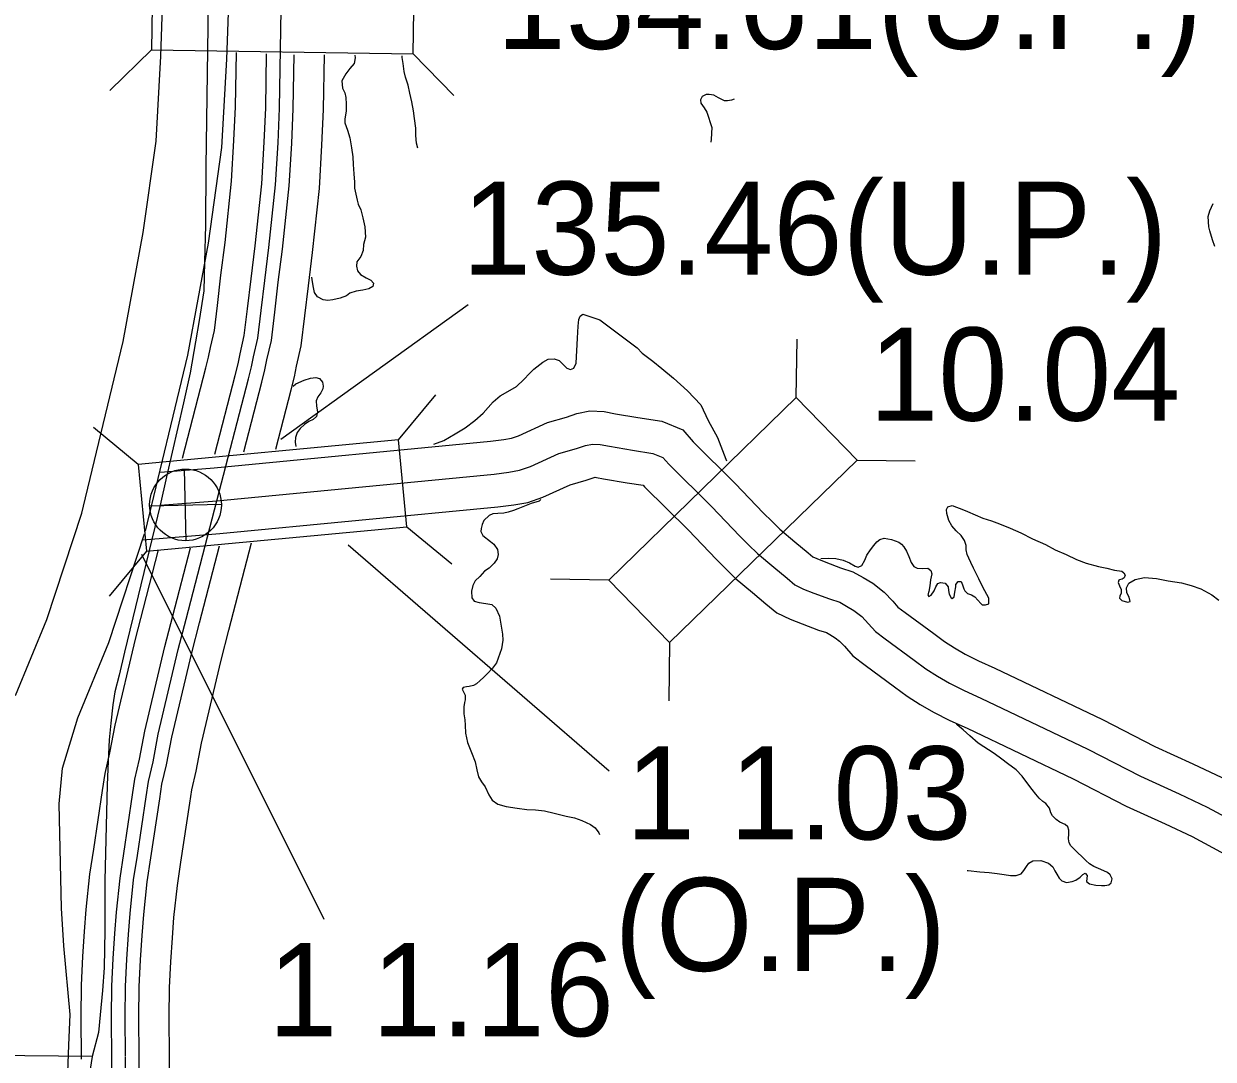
# Model space of a CAD drawing. Extents: x 31699 to 244310, y -8841 to 11474.
# Drawn here: x 103747.3 to 104107.3, y 350.4 to 663.7 of the extents above; entities that cross this region are included whole.
import ezdxf

# ---------------------------------------------------------------- set-up
doc = ezdxf.new("R2010")
doc.units = 0
for name, color, linetype in [('B_Logo', 7, 'Continuous'), ('Level 21', 7, 'Continuous'), ('New Level (0)', 7, 'Continuous'), ('R_Draft', 7, 'Continuous'), ('R_XS_EARTHWORK_STAGE1', 7, 'Continuous'), ('R_XS_EARTHWORK_STAGE2', 7, 'Continuous'), ('S_WALL', 7, 'Continuous'), ('S_WALL_ANNOT', 7, 'Continuous')]:
    doc.layers.add(name, color=color, linetype=linetype)

msp = doc.modelspace()

# ---------------------------------------------------------------- linework, layer by layer
at = {"layer": 'B_Logo'}
for points in [[(103803.15, 669.98), (103802.47, 620.45), (103802.33, 602.81), (103802.07, 591.65), (103801.83, 582.89), (103800.46, 573.97), (103799.31, 567.47), (103797.69, 558.15), (103795.72, 549.03), (103790.53, 526.68), (103788.63, 518.02), (103777.84, 473.64), (103776.24, 466.66), (103774.87, 461.63), (103774.27, 457.61), (103773.71, 452.11), (103773.13, 447.09), (103772.85, 440.61), (103772.59, 433.45), (103771.86, 404.5), (103771.87, 389.47), (103771.68, 378.04), (103771.14, 371.28), (103770.48, 363.91), (103769.91, 358.56), (103768.04, 351.3), (103761.18, 307.6)], [(103778.1, 351.48), (103778.03, 363.19), (103778.12, 372.48), (103778.5, 380.7), (103779.03, 388.13), (103779.51, 394.56), (103780.59, 404.67), (103781.72, 412.04), (103784.39, 429.86), (103785.04, 434.42), (103786.47, 440.39), (103788.04, 448.78), (103794.11, 474.35), (103796.47, 483.55), (103805.81, 519.41), (103815.33, 556.28), (103816.26, 559.91), (103816.87, 562.92), (103818.17, 568.63), (103819.22, 576.94), (103820.25, 586.04), (103821.53, 596.02), (103823.51, 614.97), (103824.28, 627.68), (103824.75, 638.18), (103825.2, 667.93)], [(103788.63, 518.02), (103805.81, 519.41), (103889.71, 527.48), (103894.1, 528.03), (103897.42, 528.63), (103900.74, 529.76), (103909.27, 533.67), (103914.58, 535.17), (103917.36, 536.09), (103919.49, 536.53), (103921.82, 536.44), (103924.64, 535.9), (103931.59, 534.69), (103937.75, 533.74), (103940.77, 532.53), (103942.55, 530.42), (103955.52, 517.64), (103964.1, 508.64), (103966.68, 506.09), (103969.4, 503.4), (103974.34, 499.28), (103978.34, 495.95), (103980.71, 493.99), (103983.34, 492.7), (103986.49, 491.49), (103991.2, 489.71), (103994.28, 488.7), (103996.37, 487.54), (103998.6, 486.18), (104000.97, 484.35), (104003.01, 482.18), (104005.12, 479.88), (104008.03, 477.6), (104016.82, 471.15), (104020.34, 468.54), (104023.85, 466.34), (104027.49, 464.2), (104031.93, 461.95), (104037.05, 459.64), (104069.35, 444.21), (104085.31, 436.03), (104097.02, 430.7), (104105.49, 426.72), (104118.09, 419.94)], [(103768.04, 351.3), (103625.41, 352.68)], [(103866.47, 45.97), (103832.32, 83.49), (103822.44, 94.79), (103816.44, 101.56), (103813.71, 104.85), (103810.89, 109.28), (103806.84, 115.55), (103802.08, 124.01), (103799.03, 130.3), (103794.94, 138.71), (103790.77, 147.52), (103787.51, 157.95), (103784, 170.78), (103782.49, 177.03), (103780.58, 186.08), (103779.27, 195.82), (103778.18, 207.96), (103777.62, 220.24), (103778.35, 252.73), (103778.59, 271.92), (103778.52, 297.11), (103778.21, 331.78), (103778.1, 351.23)]]:
    msp.add_lwpolyline(points, dxfattribs=at)
at = {"layer": 'Level 21'}
for p, q in [((103796.53, 507.3), (103796.03, 529)), ((103785.43, 517.9), (103807.13, 518.4))]:
    msp.add_line(p, q, dxfattribs=at)
msp.add_circle((103796.28, 518.15), 10.85, dxfattribs=at)
at = {"layer": 'New Level (0)'}
for points in [[(103795.37, 532.32), (103802.42, 559.61), (103803.26, 562.89), (103803.84, 565.72), (103805.02, 570.94), (103805.98, 578.52), (103807.01, 587.64), (103808.28, 597.57), (103810.22, 616.07), (103810.96, 628.38), (103811.42, 638.58), (103811.67, 655.01)], [(103805.15, 533.51), (103811.3, 557.32), (103812.2, 560.84), (103812.8, 563.8), (103814.06, 569.35), (103815.08, 577.43), (103816.11, 586.54), (103817.39, 596.51), (103819.36, 615.31), (103820.12, 627.9), (103820.58, 638.31), (103820.83, 654.63)], [(103813.94, 534.22), (103819.37, 555.24), (103820.33, 558.97), (103820.95, 562.05), (103822.28, 567.91), (103823.35, 576.44), (103824.38, 585.54), (103825.67, 595.54), (103827.67, 614.63), (103828.44, 627.47), (103828.91, 638.06), (103829.16, 654.28)], [(103823.6, 534.98), (103828.24, 552.95), (103829.26, 556.92), (103829.91, 560.13), (103831.32, 566.31), (103832.45, 575.35), (103833.48, 584.44), (103834.77, 594.48), (103836.8, 613.88), (103837.59, 626.98), (103838.08, 637.78), (103838.33, 654.27)], [(103764.77, 350.45), (103764.69, 363.22), (103764.79, 372.85), (103765.19, 381.49), (103765.73, 389.1), (103766.23, 395.76), (103767.37, 406.39), (103768.54, 414.04), (103771.2, 431.79), (103771.93, 436.91), (103773.42, 443.18), (103775, 451.55), (103781.16, 477.55), (103783.56, 486.89), (103788.16, 504.53)], [(103773.94, 350.45), (103773.86, 363.2), (103773.96, 372.59), (103774.34, 380.95), (103774.88, 388.43), (103775.36, 394.93), (103776.46, 405.2), (103777.6, 412.66), (103780.27, 430.47), (103780.95, 435.2), (103782.39, 441.26), (103783.97, 449.64), (103790.06, 475.35), (103792.44, 484.6), (103797.8, 505.2)], [(103782.27, 351.22), (103782.2, 363.18), (103782.29, 372.36), (103782.66, 380.46), (103783.19, 387.83), (103783.66, 394.18), (103784.73, 404.13), (103785.84, 411.41), (103788.52, 429.26), (103789.14, 433.64), (103790.54, 439.53), (103792.12, 447.91), (103798.15, 473.35), (103800.5, 482.51), (103806.55, 505.74)], [(103791.43, 351.22), (103791.36, 363.16), (103791.45, 372.1), (103791.81, 379.92), (103792.33, 387.16), (103792.79, 393.35), (103793.82, 402.95), (103794.91, 410.04), (103797.59, 427.94), (103798.16, 431.93), (103799.51, 437.61), (103801.09, 446.01), (103807.05, 471.16), (103809.38, 480.21), (103816.26, 506.63)], [(103860.79, 46.02), (103829.21, 80.71), (103819.31, 92.04), (103813.28, 98.85), (103810.34, 102.39), (103807.39, 107.03), (103803.27, 113.39), (103798.39, 122.08), (103795.28, 128.48), (103791.18, 136.91), (103786.88, 146), (103783.51, 156.78), (103779.97, 169.74), (103778.42, 176.11), (103776.48, 185.38), (103775.13, 195.35), (103774.02, 207.68), (103773.45, 220.19), (103774.18, 252.81), (103774.42, 271.94), (103774.36, 297.08), (103774.05, 331.75), (103773.94, 350.45)], [(103872.8, 45.21), (103835.43, 86.26), (103825.56, 97.55), (103819.6, 104.27), (103817.09, 107.31), (103814.4, 111.53), (103810.41, 117.7), (103805.78, 125.94), (103802.78, 132.12), (103798.7, 140.51), (103794.66, 149.04), (103791.51, 159.12), (103788.04, 171.82), (103786.55, 177.95), (103784.69, 186.79), (103783.41, 196.28), (103782.34, 208.24), (103781.78, 220.29), (103782.51, 252.66), (103782.76, 271.89), (103782.69, 297.13), (103782.38, 331.81), (103782.27, 351.22)], [(103884.83, 45.62), (103842.27, 92.36), (103832.45, 103.6), (103826.56, 110.24), (103824.51, 112.72), (103822.12, 116.47), (103818.26, 122.44), (103813.9, 130.19), (103811.02, 136.13), (103806.96, 144.48), (103803.22, 152.38), (103800.31, 161.7), (103796.92, 174.11), (103795.49, 179.98), (103793.73, 188.35), (103792.52, 197.31), (103791.48, 208.86), (103790.96, 220.4), (103791.68, 252.5), (103791.92, 271.85), (103791.86, 297.18), (103791.54, 331.88), (103791.43, 351.22)]]:
    msp.add_lwpolyline(points, dxfattribs=at)
at = {"layer": 'R_Draft'}
for points in [[(103847.5, 654.18), (103847.61, 653.45), (103847.31, 651.71), (103846.07, 650.22), (103844.77, 648.52), (103843.61, 646.43), (103843.85, 644.23), (103844.54, 642.77), (103844.77, 641.44), (103844.94, 639.37), (103844.91, 637.23), (103844.55, 634.95), (103844.51, 633.75), (103845.28, 631.49), (103845.99, 629.16), (103846.52, 626.17), (103846.9, 623.43), (103847.01, 621.16), (103847.2, 618.29), (103847.44, 615.76), (103847.48, 613.96), (103848.28, 610.36), (103848.57, 609.17), (103849.33, 607.38), (103849.98, 604.98), (103850.56, 602.25), (103850.75, 599.12), (103850.19, 596.97), (103850.03, 595.16), (103849.33, 593.28), (103848.16, 591.72), (103848.05, 590.38), (103848.34, 588.98), (103849.23, 587.86), (103850.98, 586.83), (103852.33, 586.18), (103853.15, 585.26), (103852.96, 584.26), (103851.78, 583.5), (103849.92, 583.13), (103847.92, 582.82), (103846.07, 582.19), (103845.01, 581.43), (103843.09, 580.73), (103840.9, 580.15), (103839.37, 579.99), (103837.96, 580.23), (103836.28, 581.07), (103835.32, 582.45), (103834.88, 584.45)], [(103866.58, 626.07), (103866.23, 627.54), (103865.99, 629.94), (103865.95, 632.15), (103865.63, 635.02), (103865.25, 637.41), (103864.8, 640.08), (103864.22, 642.67), (103863.64, 645.13), (103862.86, 647.53), (103862.43, 649.26), (103862.12, 651.65), (103861.88, 653.52), (103861.85, 654.02)], [(103962.36, 640.89), (103961.51, 640.57), (103960.31, 640.42), (103959.38, 640.4), (103957.63, 641.3), (103956.21, 642.08), (103954.74, 642.32), (103953.88, 642.3), (103952.69, 641.67), (103952.17, 640.73), (103952.26, 639.66), (103953.28, 638.28), (103954.04, 636.96), (103955.6, 632.31), (103955.39, 628.83), (103955.31, 627.85)], [(104107.81, 596.3), (104107.11, 598.29), (104106.32, 601.08), (104106.04, 602.28), (104105.84, 605.35), (104106.28, 607.09), (104107.37, 609.32)], [(103834.88, 584.45), (103834.65, 586.32), (103834.53, 587.09)], [(103871.49, 536.53), (103874.44, 537.62), (103877.87, 539.62), (103880.91, 541.42), (103883.87, 543.68), (103886.36, 545.93), (103889.37, 549.33), (103891.53, 551.17), (103893.84, 552.42), (103896.42, 553.94), (103898.71, 556.05), (103900.41, 557.89), (103901.72, 559.25), (103904.42, 561.37), (103906, 562.21), (103907.87, 562.37), (103909.34, 561.87), (103910.7, 560.56), (103911.72, 559.51), (103912.8, 559.13), (103913.86, 559.55), (103914.56, 561.03), (103914.89, 568.59), (103915.09, 572.2), (103915.38, 574.28), (103915.77, 575.29), (103916.55, 575.9), (103921.72, 574.13), (103933.02, 565.66), (103934.52, 564.08), (103937.7, 561.6), (103940.47, 559.45), (103944, 556.51), (103948.2, 552.65), (103952.22, 548.38), (103954.51, 543.68), (103957.27, 538.52), (103959.86, 531.95), (103960.03, 531.47)], [(103828.92, 554.08), (103829.7, 554.75), (103832.21, 555.93), (103834.07, 556.5), (103835.73, 556.67), (103836.81, 556.35), (103837.76, 555.23), (103837.98, 554.1), (103837.87, 553.23), (103837.22, 552.02), (103836.38, 550.8), (103835.86, 549.65), (103835.96, 548.05), (103836.26, 546.32), (103835.89, 544.91), (103834.9, 544.02), (103833.65, 543.33), (103832.33, 542.43), (103830.95, 541.27), (103830.04, 540.05), (103829.53, 538.51), (103829.49, 537.1), (103829.66, 535.8)], [(103903.83, 519.77), (103903.33, 519.25), (103900.88, 518.61), (103896.84, 516.99), (103895.51, 516.5), (103893.99, 515.94), (103892.59, 515.64), (103890.86, 515.54), (103889.33, 515.45), (103888.21, 514.89), (103886.57, 513.39), (103886.05, 512.18), (103885.74, 511.04), (103885.69, 510.1), (103886.32, 508.91), (103888.55, 507.08), (103889.63, 506.3), (103890.73, 504.65), (103890.96, 503.12), (103890.65, 501.84), (103889.67, 500.49), (103888.17, 499.05), (103886.78, 498.09), (103885.34, 496.53), (103883.97, 495.17), (103883.2, 493.75), (103882.89, 492.07), (103882.93, 490.07), (103883.68, 489.01), (103885.16, 488.57), (103887.23, 488.34), (103889.04, 487.98), (103890.26, 486.86), (103891.31, 484.48), (103891.83, 481.48), (103892.21, 479.08), (103892.37, 477.21), (103891.89, 474.6), (103890.43, 470.36), (103889.19, 468.8), (103887.69, 467.1), (103886.45, 465.88)], [(103988.53, 501.96), (103990.9, 502.07), (103993.1, 501.91), (103995.38, 501.42), (103997.26, 500.58), (103998.95, 499.61), (103999.89, 499.3), (104001.01, 499.79), (104001.85, 501.41), (104002.49, 502.95), (104003.59, 504.51), (104004.57, 505.87), (104005.48, 506.95), (104006.47, 507.71), (104007.73, 508.07), (104010.01, 507.71), (104012.16, 506.88), (104012.97, 506.29), (104013.65, 505.5), (104014.54, 504.12), (104015.17, 502.53), (104015.94, 500.67), (104016.69, 499.55), (104017.71, 498.97), (104019.24, 498.86), (104020.97, 498.96), (104021.85, 498.31), (104022.14, 497.25), (104021.77, 495.5), (104021.54, 493.63), (104021.24, 491.95), (104020.92, 490.94), (104021.26, 490.48), (104021.99, 490.83), (104022.9, 492.18), (104023.41, 493.39), (104023.99, 494.34), (104024.79, 494.69), (104026.19, 494.45), (104027.08, 493.4), (104027.17, 492.2), (104027.39, 491.13), (104028.01, 490.07), (104028.28, 489.81), (104028.94, 490.36), (104029.18, 491.77), (104029.42, 493.31), (104029.47, 494.04), (104030.19, 494.99), (104031.05, 495.01), (104031.47, 494.01), (104031.83, 492.75), (104032.11, 492.16), (104032.92, 491.3), (104034.13, 490.92), (104035.21, 490.34), (104036.09, 489.36), (104036.98, 488.31), (104037.45, 487.91), (104038.46, 487.87), (104039.38, 488.22), (104039.42, 489.95), (104038.24, 492.14), (104037.14, 494.26), (104036.37, 495.78), (104035.47, 497.63), (104034.78, 499.02), (104033.95, 500.68), (104033.32, 502.07), (104032.84, 503.13), (104032.54, 504.59), (104032.52, 505.86), (104032.09, 507.39), (104031, 508.84), (104029.57, 510.28), (104028.2, 511.86), (104027.31, 513.45), (104026.74, 515.51), (104026.65, 516.78), (104027.03, 517.59), (104028.36, 518.01)], [(104028.36, 518.01), (104031.79, 516.61), (104033, 516.1), (104035.28, 515.14), (104037.57, 514.18), (104040.25, 513.36), (104042.67, 512.4), (104045.9, 511.06), (104049.12, 509.65), (104052.69, 507.91), (104056.53, 506.12), (104059.49, 504.57), (104062.85, 503.1), (104065.95, 501.62), (104068.9, 500.54), (104072.59, 499.54), (104075.14, 498.98), (104077.48, 498.43), (104079.69, 498.07), (104080.3, 497.61), (104080.64, 496.88), (104080.39, 496.08), (104079.8, 495.66), (104078.94, 495.51), (104078.74, 495.38), (104078.55, 494.71), (104078.97, 493.64), (104079.46, 492.58), (104079.48, 491.45), (104079.03, 490.57), (104078.97, 489.97), (104079.65, 489.25), (104081.4, 488.68), (104082.19, 488.96), (104081.9, 490.22), (104081.21, 491.55), (104081.05, 493.08), (104081.76, 494.43), (104083.67, 495.6), (104086.53, 496.19), (104090.14, 495.86), (104093.75, 495.13), (104097.76, 494.53), (104100.65, 493.79), (104103.6, 492.71), (104106.9, 490.96), (104109.07, 489.34)], [(103886.45, 465.88), (103885.46, 464.99), (103884.35, 464.03), (103883.42, 463.48), (103882.16, 463.19), (103881.36, 463.11), (103880.37, 462.95), (103879.98, 462.35), (103880.46, 461.62), (103880.88, 460.56), (103880.97, 459.22), (103880.72, 458.35), (103880.54, 457.01), (103880.51, 454.94), (103880.82, 453.07), (103880.91, 451.54), (103881.02, 449.07), (103881.61, 446.27), (103882.87, 443.22), (103883.99, 440.37), (103884.43, 438.04), (103885, 435.84), (103885.83, 434.39), (103887, 432.81), (103888.11, 430.42), (103889.07, 428.84), (103890.83, 427.6), (103893.31, 426.91), (103896.65, 426.38), (103899.6, 425.96), (103902.2, 425.88), (103904.94, 425.6), (103907.89, 424.85), (103911.51, 423.98), (103914.05, 423.43), (103916.2, 422.67), (103918.82, 421.45), (103920.31, 420.41), (103921.41, 418.89), (103921.63, 418.42)], [(104032.91, 407.57), (104033.21, 407.58), (104036.69, 407.17), (104039.49, 406.89), (104041.9, 406.61), (104044.11, 406.31), (104045.98, 406.01), (104047.71, 406.05), (104049.17, 406.54), (104050.02, 407.56), (104050.86, 408.78), (104051.58, 409.8), (104052.77, 410.49), (104055.17, 410.6), (104057.52, 409.77), (104058.8, 408.66), (104059.43, 407.47), (104060.05, 406.41), (104060.67, 405.22), (104061.55, 404.37), (104062.96, 403.93), (104064.62, 404.23), (104065.75, 404.65), (104067.07, 405.48), (104067.85, 406.29), (104068.58, 406.71), (104069.19, 406.05), (104068.96, 404.24), (104069.91, 403.46), (104071.78, 403.09), (104073.52, 402.99), (104074.52, 403.01), (104075.71, 403.24), (104076.44, 403.78), (104076.75, 405.06), (104076.19, 406.19), (104075.38, 406.9), (104073.36, 407.87), (104071.21, 408.76), (104069.93, 409.54), (104068.77, 410.59), (104067.42, 411.83), (104066.46, 412.82), (104065.17, 414.06), (104064.29, 414.98), (104063.74, 415.91), (104063.52, 417.1), (104063.62, 418.58), (104063.6, 419.71), (104063.38, 420.71), (104062.57, 421.5), (104060.95, 422.2), (104059.81, 422.92), (104058.65, 424.1), (104058.23, 425.02), (104057.81, 426.35), (104056.71, 427.8), (104055.77, 428.45), (104054.62, 429.43), (104053.66, 430.62), (104052.57, 432.07), (104050.93, 434.17), (104049.49, 436.08), (104047.72, 437.99), (104045.08, 439.94), (104043.33, 441.18), (104041.02, 442.94), (104036.16, 446.06), (104033.72, 448.28), (104031.62, 450.11), (104029.79, 451.62), (104029.65, 451.74)]]:
    msp.add_lwpolyline(points, dxfattribs=at)
at = {"layer": 'R_XS_EARTHWORK_STAGE1'}
for p, q in [((103786.02, 655.78), (103773.39, 643.53)), ((103865.21, 654.59), (103877.47, 641.96)), ((103981.13, 550.64), (103981.37, 568.24)), ((103860.8, 537.84), (103872.02, 551.4)), ((103781.95, 530.38), (103768.39, 541.6)), ((103999.54, 531.72), (104017.14, 531.48)), ((103863.29, 511.56), (103876.85, 500.34)), ((103784.44, 504.1), (103773.22, 490.54)), ((103924.37, 495.41), (103906.77, 495.65)), ((103942.78, 476.48), (103942.54, 458.89))]:
    msp.add_line(p, q, dxfattribs=at)
for points in [[(103865.61, 680.99), (103786.42, 682.18), (103786.02, 655.78), (103865.21, 654.59)], [(103981.13, 550.64), (103924.37, 495.41), (103942.78, 476.48), (103999.54, 531.72)], [(103860.8, 537.84), (103781.95, 530.38), (103784.44, 504.1), (103863.29, 511.56)]]:
    msp.add_lwpolyline(points, close=True, dxfattribs=at)
at = {"layer": 'R_XS_EARTHWORK_STAGE2'}
for points in [[(103806.54, 878.79), (103801.79, 841.86), (103800.78, 833.53), (103799.42, 825.9), (103798.1, 817.3), (103797.02, 805.47), (103796.36, 797.98), (103795.25, 786.02), (103793.47, 766.82), (103792, 745.97), (103790.53, 722.8), (103790.17, 695.78), (103788.72, 653.86), (103787.3, 628.24), (103783.39, 600.54), (103777.3, 567.6), (103764.65, 514.83)], [(103826.37, 876.24), (103821.64, 839.38), (103820.57, 830.56), (103819.15, 822.63), (103817.97, 814.88), (103816.94, 803.68), (103816.28, 796.18), (103815.17, 784.17), (103813.4, 765.19), (103811.96, 744.63), (103810.52, 722.04), (103810.16, 695.3), (103808.7, 652.97), (103807.22, 626.29), (103803.14, 597.33), (103796.88, 563.45), (103784.1, 510.17)], [(103788.76, 528.06), (103804.93, 529.37), (103888.6, 537.42), (103892.59, 537.92), (103894.91, 538.34), (103897.03, 539.06), (103905.8, 543.08), (103911.64, 544.73), (103914.77, 545.77), (103918.65, 546.57), (103922.98, 546.41), (103926.45, 545.73), (103933.21, 544.56), (103940.41, 543.45), (103946.81, 540.88), (103949.9, 537.22), (103962.65, 524.65), (103971.24, 515.65), (103973.71, 513.19), (103976.12, 510.81), (103980.74, 506.97), (103984.73, 503.64), (103986.17, 502.45), (103987.33, 501.88), (103990.05, 500.84), (103994.53, 499.14), (103998.31, 497.9), (104001.41, 496.17), (104004.28, 494.42), (104007.7, 491.78), (104010.33, 488.99), (104011.93, 487.25), (104014.08, 485.57), (104022.76, 479.2), (104025.98, 476.81), (104029.04, 474.89), (104032.29, 472.98), (104036.26, 470.97), (104041.26, 468.71), (104073.79, 453.18), (104089.66, 445.03), (104101.21, 439.78), (104109.99, 435.66)], [(103783.32, 507.56), (103806.69, 509.45), (103890.81, 517.54), (103895.61, 518.14), (103899.94, 518.92), (103904.44, 520.46), (103912.73, 524.25), (103917.51, 525.61), (103919.96, 526.42), (103920.32, 526.49), (103920.67, 526.48), (103922.83, 526.06), (103929.98, 524.82), (103934.82, 524.07), (103935.2, 523.62), (103948.39, 510.62), (103956.96, 501.64), (103959.64, 498.98), (103962.67, 495.99), (103967.94, 491.6), (103971.95, 488.25), (103975.25, 485.53), (103979.34, 483.53), (103982.93, 482.15), (103987.87, 480.28), (103990.26, 479.5), (103991.33, 478.9), (103992.92, 477.93), (103994.23, 476.91), (103995.69, 475.37), (103998.3, 472.52), (104001.98, 469.63), (104010.89, 463.1), (104014.69, 460.28), (104018.66, 457.79), (104022.69, 455.42), (104027.61, 452.93), (104032.83, 450.57), (104064.91, 435.25), (104080.96, 427.02), (104092.82, 421.63), (104101, 417.78), (104113.23, 411.2)], [(103744.8, 460.49), (103754.28, 483.47), (103764.88, 515.63)], [(103746.95, 186.71), (103747.77, 196.08), (103750.03, 229.42), (103753.29, 274.3), (103758.35, 324.57), (103760.57, 343.78), (103760.95, 354.68), (103761.34, 364.01), (103759.48, 384.78), (103758.77, 396.16), (103758.06, 427.73), (103759.01, 438.49), (103763.65, 453.74), (103773.05, 476.52), (103783.88, 509.37)]]:
    msp.add_lwpolyline(points, dxfattribs=at)
at = {"layer": 'S_WALL'}
for p, q in [((103881.84, 578.64), (103825.18, 537.97)), ((103924.5, 437.56), (103845.52, 506.01))]:
    msp.add_line(p, q, dxfattribs=at)
at = {"layer": 'S_WALL_ANNOT'}
msp.add_line((103838.25, 392.69), (103783.05, 503.1), dxfattribs=at)

# ---------------------------------------------------------------- texts
at = {"layer": 'S_WALL'}
for s, height, p in [('134.61(U.P.)', 28.1599, (103890.44, 656.09)), ('135.46(U.P.)', 28.1599, (103879.98, 587.81)), ('10.04', 28.16, (104003.18, 543.64)), ('1 1.03', 28.16, (103929.55, 416.94)), ('(O.P.)', 28.16, (103926.11, 377.16))]:
    msp.add_text(s, height=height, dxfattribs=at).set_placement(p)
at = {"layer": 'S_WALL_ANNOT'}
msp.add_text('1 1.16', height=28.16, dxfattribs=at).set_placement((103821.28, 357.41))

doc.saveas('drawing.dxf')
